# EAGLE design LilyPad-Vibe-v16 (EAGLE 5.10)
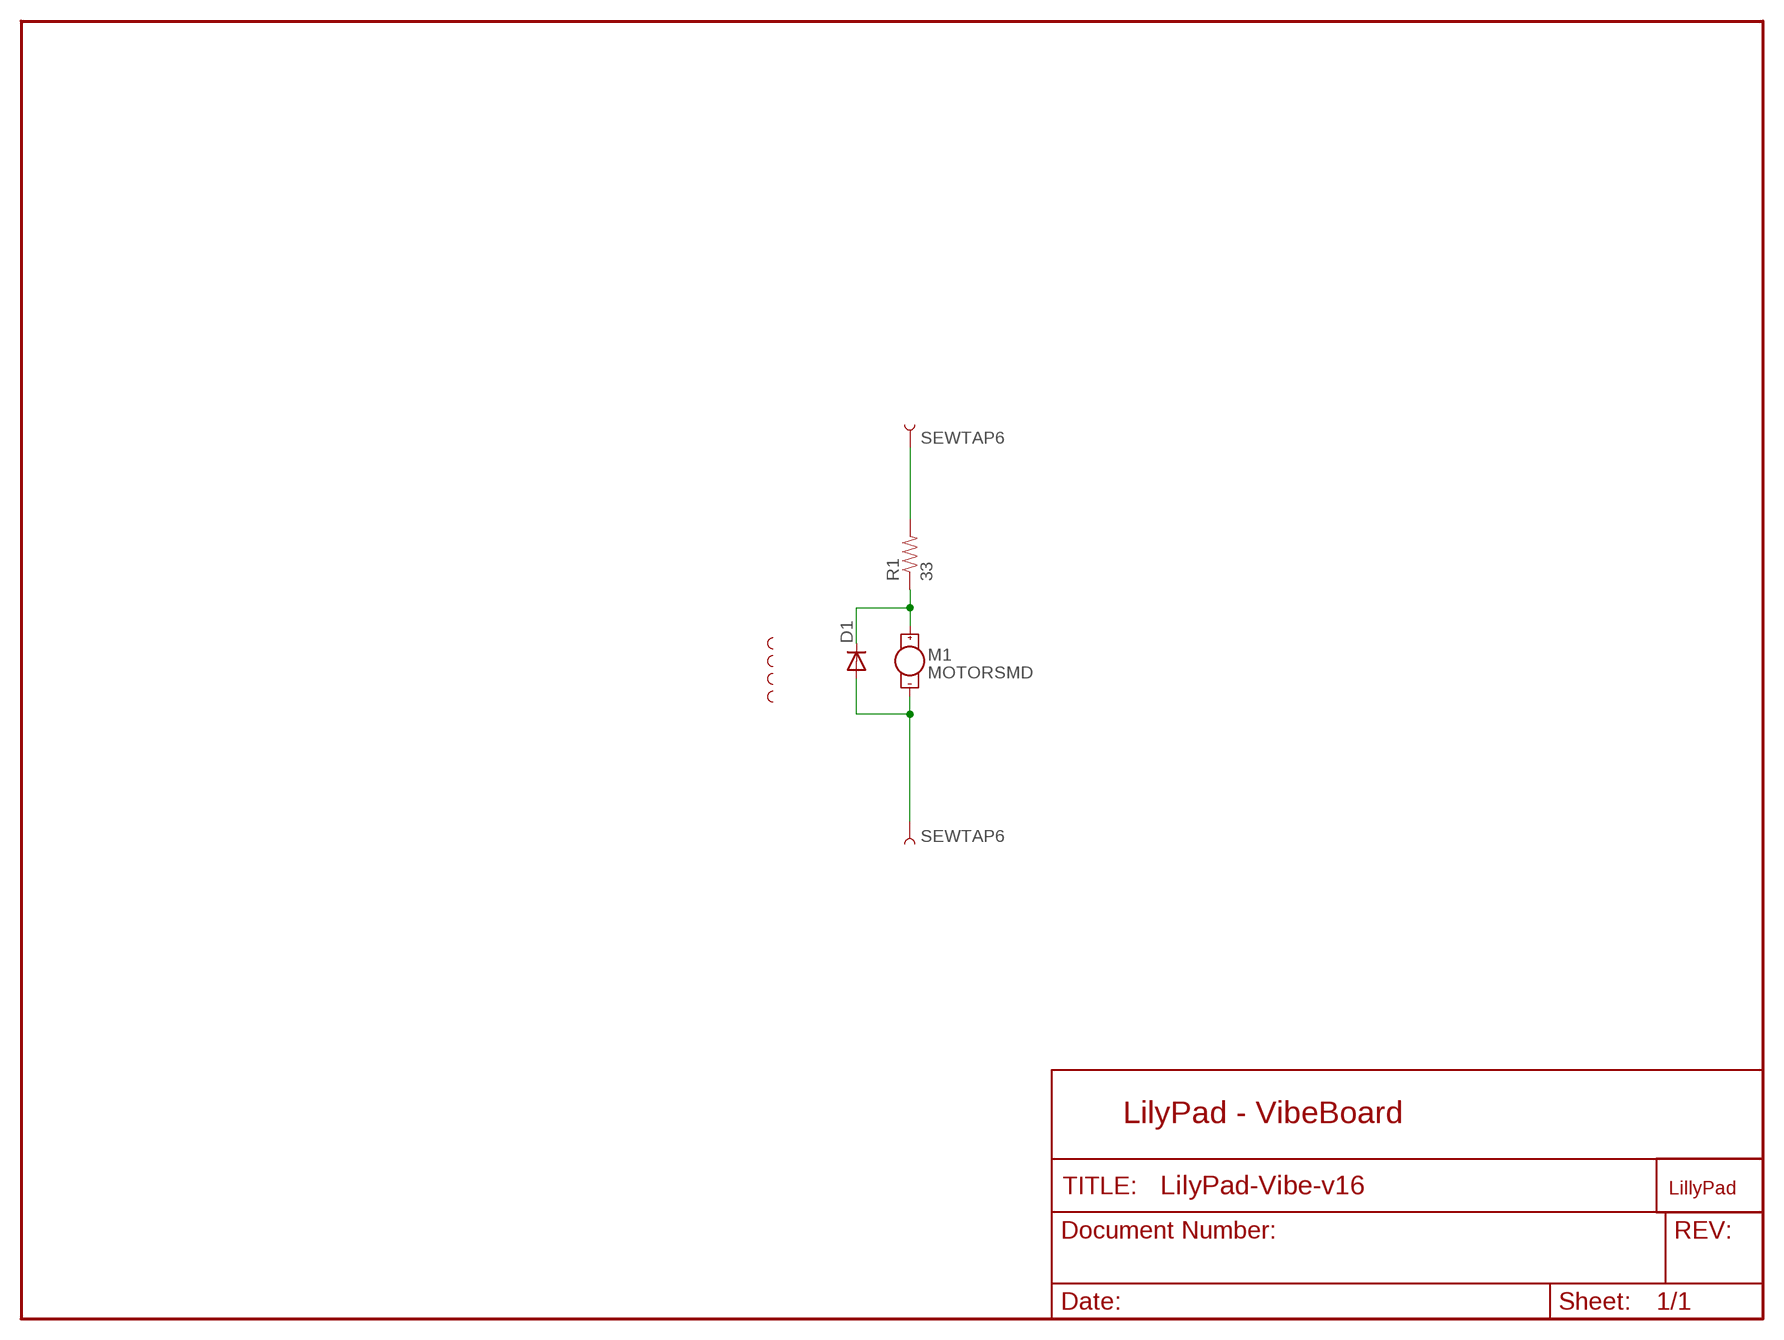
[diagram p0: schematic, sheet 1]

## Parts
D1  DIODESOD  [SOD-323]
M1  MOTORSMD  [VIBE-MOTOR-10MM-SMD]
R1  33  RESISTOR0402-RES  [0402-RES]
U$2  LOGO-LPLP  [LOGO-LILYPAD]
VIBE1  SEWTAP-NOHOLE2  [PETAL-NOHOLE-2SIDE]
VIBE2  SEWTAP-NOHOLEW-MASK  [PETAL-NOHOLE-2SIDE-SPECIAL-W-MASK]
VIBE3  SEWTAP-NOHOLE2  [PETAL-NOHOLE-2SIDE]
VIBE4  SEWTAP-NOHOLE2  [PETAL-NOHOLE-2SIDE]
VIBE+  SEWTAP6  [PETAL-SMALL-2SIDE]
VIBE-  SEWTAP6  [PETAL-SMALL-2SIDE]

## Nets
5V: R1.2 VIBE+.1
GND: D1.2(A) M1.P$2(-) VIBE-.1
N$1: D1.1(C) M1.P$1(+) R1.1

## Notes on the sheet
- LilyPad - VibeBoard

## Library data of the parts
D1 = SparkFun:DIODE: Diode
M1 = Testing:MOTOR: Vibration Motor
R1 = SparkFun:RESISTOR: Resistor
U$2 = LilyPad-Wearables:LOGO-LP
VIBE1 VIBE3 VIBE4 = LilyPad-Wearables:SEWTAP-NOHOLE
VIBE2 = Testing:SEWTAP-NOHOLE
VIBE+ VIBE- = LilyPad-Wearables:SEWTAP

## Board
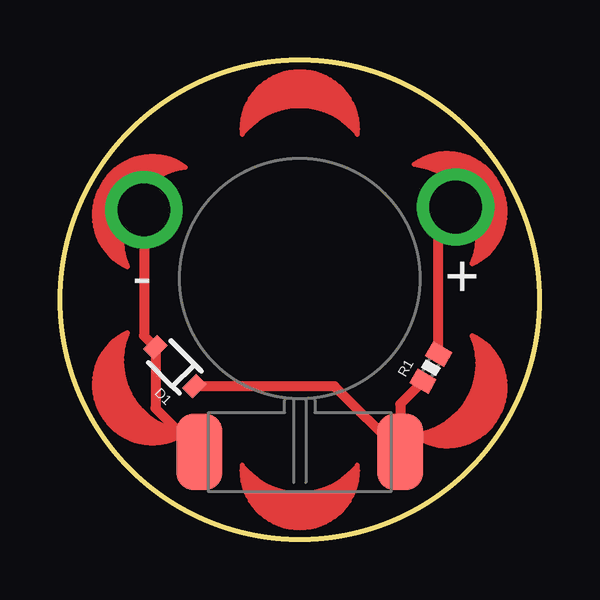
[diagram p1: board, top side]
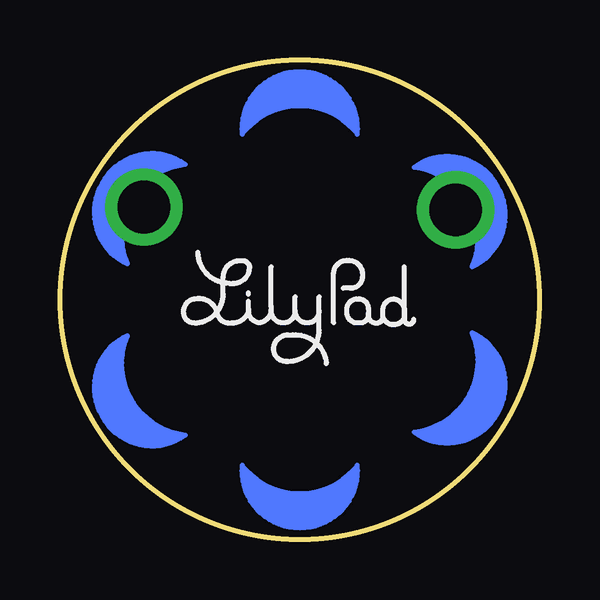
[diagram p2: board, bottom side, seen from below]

Size 20 x 20 mm. Coordinates in mm from the lower left corner, seen from the top.
Outline: circle at 10,10 radius 10
Copper layers (1*16): Top 0.035mm / dielectric 1.5mm / Bottom 0.035mm
Design rules "SparkFun": minimum track width 8mil, minimum drill 20mil, track to track 8mil, track to pad 8mil, pad to pad 8mil, via to via 8mil, smd to smd 8mil, copper to edge 8mil, drill to drill 8mil, minimum pad ring 12mil, minimum via ring 10mil, stop-mask expansion 4mil, vias tented up to drill 20mil, thermal gap 10mil

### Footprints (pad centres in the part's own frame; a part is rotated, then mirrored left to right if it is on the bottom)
SOD-323 = smd 0.63 x 0.83: 1 -1.15,0; 2 1.15,0
VIBE-MOTOR-10MM-SMD = smd 1.905 x 3.175: P$1 4.191,-7.239; P$2 -4.191,-7.239
0402-RES = smd 0.7 x 0.9: 1 -0.65,0; 2 0.65,0
PETAL-SMALL-2SIDE = drill 2.2 round: 1 0,0

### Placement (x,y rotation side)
D1  4.79,7.21 135 top
M1  10,10.89 0 top
R1  15.47,7.17 60 top
U$2  10,10 0 bottom
VIBE1  3.5,6.25 300 top
VIBE2  10,2.5 0 top
VIBE3  16.5,6.13 60 top
VIBE4  10,17.5 180 top
VIBE+  16.5,13.87 120 top
VIBE-  3.5,13.75 240 top

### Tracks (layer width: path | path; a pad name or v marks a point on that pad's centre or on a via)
5V
  Top 0.406: VIBE+.1 15.79,13.16 R1.2
GND
  Top 0.406: M1.P$2 3.98,5.48 D1.2 3.5,8.5 VIBE-.1
N$1
  Top 0.406: R1.1 14.19,5.65 M1.P$1 11.45,6.39 D1.1

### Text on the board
tPlace: + | -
